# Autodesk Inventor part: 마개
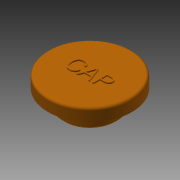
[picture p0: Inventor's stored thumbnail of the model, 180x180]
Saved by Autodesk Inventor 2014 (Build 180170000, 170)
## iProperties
Created: 2018-03
Part Number: 마개
Material: 고무
Document SubType Name: Modeling
Designer: mduedu
Density: 1 g/cm^3
Appearance: 주황색
Author: mduedu
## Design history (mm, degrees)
sketch "스케치1"
  geometry: C1 r 17 at (0, 0); 1 further point
  constraints: 1 centre point, 1 coincident
  dimensions: "d21" = 34 diameter of C1
extrude "돌출1" new body sketch "스케치1" distance "d2" = 6; taper "d3" = 0 deg
fillet "모깎기4" dims "d22" = 1
sketch "스케치6"
  geometry: C1 r 11 at (0, 0); 1 further point
  constraints: 1 centre point, 1 coincident
  dimensions: "d23" = 22 diameter of C1
extrude "돌출5" join sketch "스케치6" distance "d24" = 6; taper "d25" = 0 deg
sketch "스케치7"
  geometry: C1 r 7.5 at (0, 0); 1 further point
  constraints: 1 centre point, 1 coincident
  dimensions: "d26" = 15 diameter of C1
extrude "돌출6" cut sketch "스케치7" distance "d27" = 6; taper "d28" = 0 deg
sketch "스케치8"
  geometry: C1 r 17 at (0, 0) reference; C2 r 14 at (0, 0); 1 further point
  constraints: 1 centre point, 1 coincident
  dimensions: "d37" = 28 diameter of C2
extrude "돌출7" cut sketch "스케치8" distance "d30" = 1; taper "d31" = 0 deg
fillet "모깎기5" dims "d32" = 1
chamfer "모따기2" distance "d33" = 1; stored, may be unused: second distance "d34" = 2, angle "d35" = 45 deg
sketch "스케치5"
  geometry: 2 further points
  constraints: 1 coincident, 1 other
feature "엠보싱1" sketch "스케치5" dims "d19" = 0.5, "d20" = 0
node "솔리드1"
